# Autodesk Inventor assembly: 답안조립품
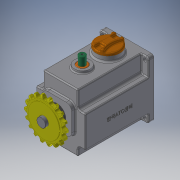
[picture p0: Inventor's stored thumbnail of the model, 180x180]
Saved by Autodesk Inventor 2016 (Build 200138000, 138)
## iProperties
Created: 2017-12
Part Number: 답안조립품
Material: 일반
Document SubType Name: Assembly
Designer: 605-06
Author: 605-06
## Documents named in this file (17)
- C:\Users\605-06\Desktop\371207V1018\답안조립품.iam
- C:\Users\605-06\Desktop\371207V1018\본체.ipt
- C:\Users\605-06\Desktop\371207V1018\볼트 M4 x 10.ipt
- C:\Users\605-06\Desktop\371207V1018\오일 실 8 22 7.ipt
- C:\Users\605-06\Desktop\371207V1018\커버.ipt
- C:\Users\605-06\Desktop\371207V1018\상부 캡.ipt
- C:\Users\605-06\Desktop\371207V1018\가변스프링.ipt
- C:\Users\605-06\Desktop\371207V1018\부시.ipt
- C:\Users\605-06\Desktop\371207V1018\슬라이더.ipt
- C:\Users\605-06\Desktop\371207V1018\베어링 608.ipt
- C:\Users\605-06\Desktop\371207V1018\멈춤나사 M3x8.ipt
- C:\Users\605-06\Desktop\371207V1018\메인축.ipt
- C:\Users\605-06\Desktop\371207V1018\서브축.ipt
- C:\Users\605-06\Desktop\371207V1018\키 5 x 5 x 18.ipt
- C:\Users\605-06\Desktop\371207V1018\베어링 6003.ipt
- C:\Users\605-06\Desktop\371207V1018\스프로킷.ipt
- C:\Users\605-06\Desktop\371207V1018\오일 실 17 32 8.ipt
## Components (1 placed, 1 different names)
1. 가변스프링:1
